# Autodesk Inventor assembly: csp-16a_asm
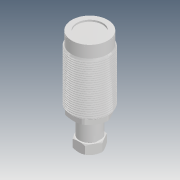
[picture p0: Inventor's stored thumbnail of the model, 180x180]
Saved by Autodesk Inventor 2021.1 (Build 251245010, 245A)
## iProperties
Created: 2019-04
Part Number: csp-16a_asm
Description: STEP AP214
Document SubType Name: Assembly
Designer: user
Title: csp-16a_asm.STEP
Revision Number: ÈÎºÎ
Sending System: SolidWorks 2016
Preprocessor: SwSTEP 2.0
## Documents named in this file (7)
- D:\Vault_2016\Projekty\Clamptek\Hydraulic\CSP-16\Inventor\CSP-16A\csp-16a_asm.iam
- D:\Vault_2016\Projekty\Clamptek\Hydraulic\CSP-16\Inventor\CSP-16A\CSP-16AHG.ipt
- D:\Vault_2016\Projekty\Clamptek\Hydraulic\CSP-16\Inventor\CSP-16A\CSP-16HSG.ipt
- D:\Vault_2016\Projekty\Clamptek\Hydraulic\CSP-16\Inventor\CSP-16A\M4X10.ipt
- D:\Vault_2016\Projekty\Clamptek\Hydraulic\CSP-16\Inventor\CSP-16A\CSP-16BT.ipt
- D:\Vault_2016\Projekty\Clamptek\Hydraulic\CSP-16\Inventor\CSP-16A\CP-16DP.ipt
- D:\Vault_2016\Projekty\Clamptek\Hydraulic\CSP-16\Inventor\CSP-16A\CSP-16LS.ipt
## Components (6 placed, 6 different names)
1. CSP-16AHG_1
2. CSP-16HSG_2
3. M4X10_3
4. CSP-16BT_4
5. CP-16DP_5
6. CSP-16LS_6
